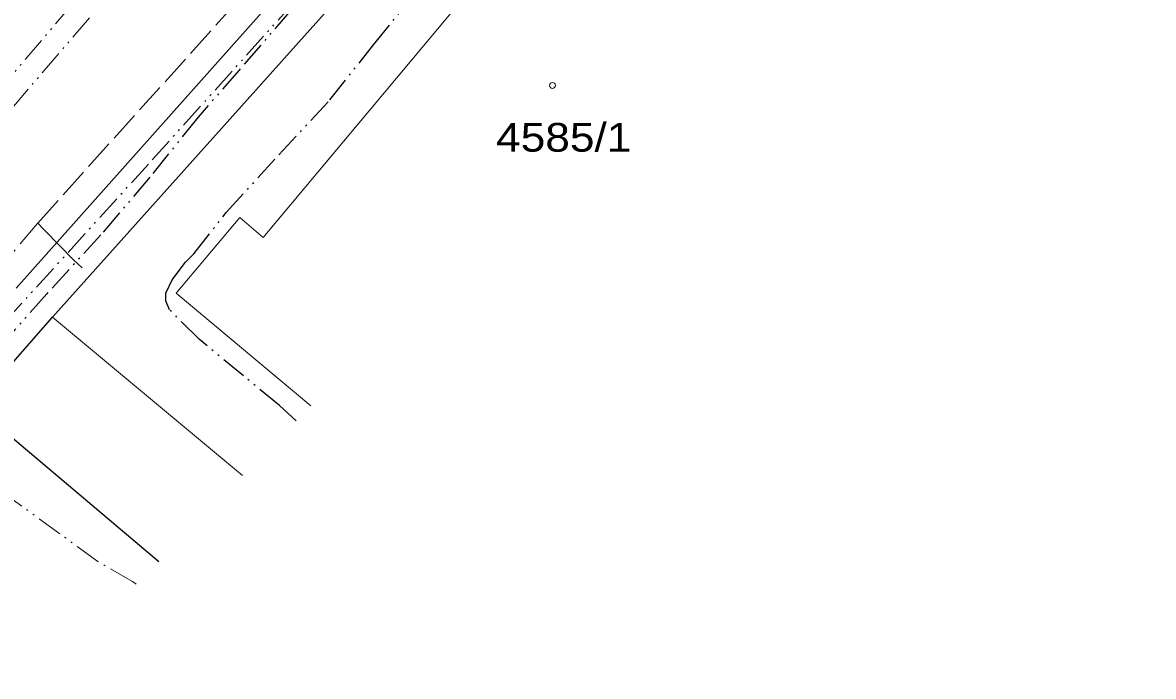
# Model space of a CAD drawing. Extents: x -683947 to -683762, y -1065756 to -1065543.
# Drawn here: x -683844 to -683777.1, y -1065654 to -1065615.3 of the extents above; entities that cross this region are included whole.
import ezdxf

# ---------------------------------------------------------------- set-up
doc = ezdxf.new("R2010")
doc.units = 0
doc.header["$LTSCALE"] = 0.3
doc.linetypes.add('DASH_DOUBLE_DOT', pattern=[9.2, 5, -1.2, 0.3, -1.2, 0.3, -1.2])
doc.linetypes.add('LONG_DASHED', pattern=[7.5, 6, -1.5])
for name, color, linetype, lineweight in [('1', 7, 'Continuous', 25), ('31', 7, 'DASH_DOUBLE_DOT', 13), ('35', 7, 'LONG_DASHED', 13), ('36', 7, 'DASH_DOUBLE_DOT', 25), ('4', 7, 'Continuous', 13), ('41', 7, 'DASH_DOUBLE_DOT', 13), ('46', 7, 'DASH_DOUBLE_DOT', 13), ('5', 7, 'Continuous', 13), ('50', 7, 'LONG_DASHED', 13)]:
    doc.layers.add(name, color=color, linetype=linetype, lineweight=lineweight)
doc.layers.add('2', color=7, linetype='Continuous')

msp = doc.modelspace()

# ---------------------------------------------------------------- linework, layer by layer
at = {"layer": '1'}
for p, q in [((-683844.35, -1065631.04), (-683799.69, -1065580.85)), ((-683809.1, -1065595.75), (-683842.21, -1065632.76)), ((-683846.81, -1065638), (-683842.21, -1065632.76)), ((-683846.81, -1065638), (-683835.924, -1065647.198))]:
    msp.add_line(p, q, dxfattribs=at)
at = {"layer": '31'}
msp.add_lwpolyline([(-683837.249, -1065648.554), (-683837.47, -1065648.39), (-683839.53, -1065647.2), (-683846.53, -1065642.1), (-683847.26, -1065641.82)], dxfattribs=at)
at = {"layer": '35'}
msp.add_lwpolyline([(-683896.24, -1065687.55), (-683894.71, -1065685.72), (-683893.48, -1065684.13), (-683891.61, -1065681.955), (-683887.89, -1065677.63), (-683886.16, -1065675.53), (-683853.44, -1065639.1), (-683848.45, -1065633.59), (-683843.114, -1065627.22), (-683843.08, -1065627.18), (-683831.4, -1065614.21), (-683820.06, -1065601.41), (-683812.91, -1065593.55), (-683807.75, -1065587.62), (-683793.84, -1065572.21), (-683791.969, -1065570.179), (-683790.708, -1065568.809), (-683790.074, -1065568.129)], dxfattribs=at)
at = {"layer": '36', "lineweight": 13}
msp.add_lwpolyline([(-683853.405, -1065628.437), (-683847.424, -1065621.75), (-683837.692, -1065610.319), (-683826.563, -1065598.101), (-683821.765, -1065592.734), (-683810.241, -1065579.722), (-683798.152, -1065565.762), (-683797.335, -1065564.872), (-683796.84, -1065564.29)], dxfattribs=at)
at = {"layer": '36'}
for points in [[(-683827.805, -1065638.885), (-683828.78, -1065637.97), (-683830.92, -1065636.23), (-683833.53, -1065634.06), (-683835.29, -1065632.31), (-683835.5, -1065631.78), (-683835.5, -1065631.33), (-683835.12, -1065630.55), (-683834.34, -1065629.49), (-683833.84, -1065629), (-683831.94, -1065626.56), (-683828.817, -1065623.147), (-683825.805, -1065619.899), (-683823.226, -1065616.647), (-683821.28, -1065614.232), (-683819.465, -1065612.274), (-683818.198, -1065611.186), (-683816.844, -1065611.315)], [(-683828.07, -1065614.55), (-683831.17, -1065618.13), (-683833.59, -1065620.92), (-683836.45, -1065624.46), (-683839.34, -1065627.88), (-683842.53, -1065631.36), (-683845.66, -1065634.87)]]:
    msp.add_lwpolyline(points, dxfattribs=at)
at = {"layer": '4'}
for p, q in [((-683834.89, -1065631.34), (-683826.939, -1065637.998)), ((-683842.21, -1065632.76), (-683830.969, -1065642.124))]:
    msp.add_line(p, q, dxfattribs=at)
msp.add_lwpolyline([(-683834.89, -1065631.34), (-683831.13, -1065626.86), (-683829.74, -1065628.03), (-683816.21, -1065611.83)], dxfattribs=at)
at = {"layer": '41', "lineweight": 25}
msp.add_lwpolyline([(-683907.26, -1065705.67), (-683893.37, -1065687.98), (-683887.71, -1065681.96), (-683876.81, -1065669.67), (-683869.01, -1065660.17), (-683861.43, -1065651.54), (-683852.89, -1065642.04), (-683845.02, -1065633.03), (-683836.31, -1065623.45), (-683820.34, -1065605.7), (-683789.54, -1065571.05), (-683781.76, -1065562.31), (-683777.124, -1065557.504)], dxfattribs=at)
at = {"layer": '46'}
msp.add_lwpolyline([(-683852.585, -1065629.704), (-683846.423, -1065622.515), (-683835.949, -1065610.295), (-683830.355, -1065603.769), (-683826.197, -1065598.918)], dxfattribs=at)
at = {"layer": '5'}
msp.add_circle((-683812.647, -1065619.039), 0.175, dxfattribs=at)
at = {"layer": '50'}
msp.add_lwpolyline([(-683843.08, -1065627.18), (-683842.707, -1065627.561), (-683841.76, -1065628.53), (-683840.97, -1065629.35), (-683840.45, -1065629.84)], dxfattribs=at)

# ---------------------------------------------------------------- texts
at = {"layer": '2', "width": 1.15}
msp.add_text('4585/1', height=1.7, dxfattribs=at).set_placement((-683815.98, -1065622.96))

doc.saveas('drawing.dxf')
